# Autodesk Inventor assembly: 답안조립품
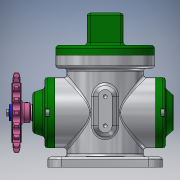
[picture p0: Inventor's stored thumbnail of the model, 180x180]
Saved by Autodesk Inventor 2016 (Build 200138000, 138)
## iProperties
Created: 2021-03
Part Number: 답안조립품
Material: 일반
Document SubType Name: Weldment
Designer: WIN7
Weld Material: Welded Aluminum-6061
Author: WIN7
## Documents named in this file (19)
- C:\Users\WIN7\Desktop\710306V1008\답안조립품.iam
- C:\Users\WIN7\Desktop\710306V1008\본체.ipt
- C:\Users\WIN7\Desktop\710306V1008\E-링.ipt
- C:\Users\WIN7\Desktop\710306V1008\덮개.ipt
- C:\Users\WIN7\Desktop\710306V1008\뒤커버.ipt
- C:\Users\WIN7\Desktop\710306V1008\링크.ipt
- C:\Users\WIN7\Desktop\710306V1008\멈춤나사 M3.ipt
- C:\Users\WIN7\Desktop\710306V1008\베어링 17 x 40 x 12.ipt
- C:\Users\WIN7\Desktop\710306V1008\볼트 M4 x 8.ipt
- C:\Users\WIN7\Desktop\710306V1008\볼트 M4 x 10.ipt
- C:\Users\WIN7\Desktop\710306V1008\스프로킷.ipt
- C:\Users\WIN7\Desktop\710306V1008\슬라이더.ipt
- C:\Users\WIN7\Desktop\710306V1008\앞커버.ipt
- C:\Users\WIN7\Desktop\710306V1008\오일 실 17 30 8.ipt
- C:\Users\WIN7\Desktop\710306V1008\와셔 4x16.ipt
- C:\Users\WIN7\Desktop\710306V1008\클레비스 핀 6 x 22.ipt
- 클레비스 핀 6 x 22.ipt
- C:\Users\WIN7\Desktop\710306V1008\키 4 x 4 x 12.ipt
- C:\Users\WIN7\Desktop\710306V1008\편심축.ipt
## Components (1 placed, 1 different names)
1. E-링:2
